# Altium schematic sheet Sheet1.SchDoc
size B; SheetNumber: 1; SheetTotal: 2
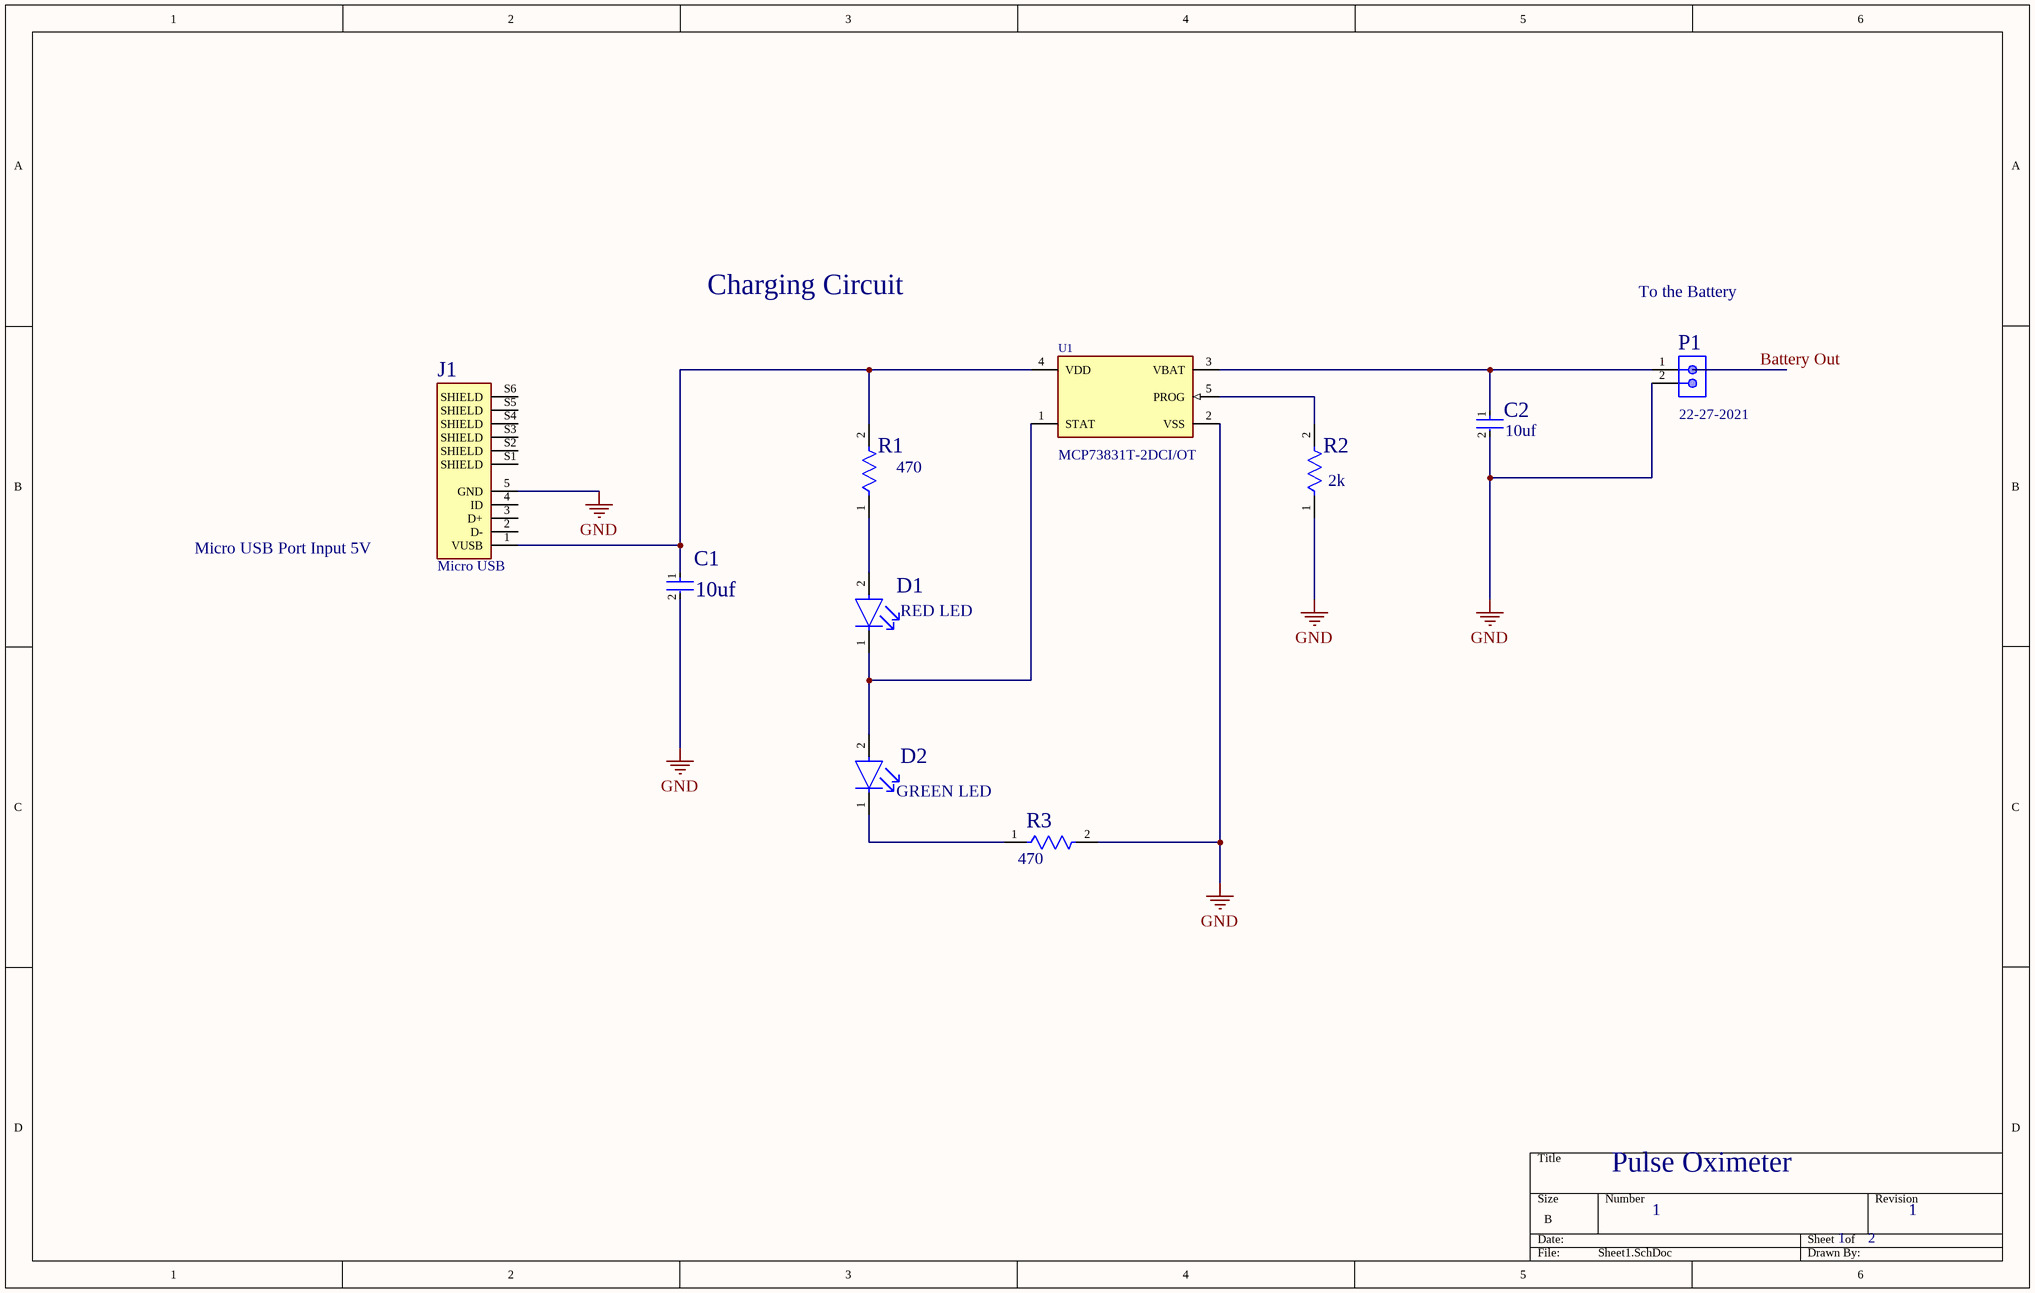
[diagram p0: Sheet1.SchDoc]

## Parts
C1  10uf  [FP-CL10-IPC_A]
C2  10uf  [FP-CL10-IPC_A]
D1  RED LED  [FP-HSMS-C150-MFG]
D2  GREEN LED  [FP-HSMG-C150-MFG]
J1  Micro USB  [AMPHENOL_10118193-0001LF]
P1  22-27-2021  [MOLX-22-27-2021_V]
R1  470  [FP-RC1608-MFG]
R2  2k  [FP-RC1608-MFG]
R3  470  [FP-RC1608-MFG]
U1  MCP73831T-2DCI/OT  [FP-C04-091-OT-IPC_B]

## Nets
GND: C1.2 C2.2 J1.5(GND) P1.2 R2.1 R3.2 U1.2(VSS)
NetC1_1: C1.1 J1.1(VUSB) R1.2 U1.4(VDD)
NetC2_1: C2.1 P1.1 U1.3(VBAT)
NetD1_1: D1.1(C) D2.2(A) U1.1(STAT)
NetD1_2: D1.2(A) R1.1
NetD2_1: D2.1(C) R3.1
NetR2_2: R2.2 U1.5(PROG)

Not connected (* = marked no-connect by the designer): J1 2(D-) 3(D+) 4(ID) S1(SHIELD) S2(SHIELD) S3(SHIELD) S4(SHIELD) S5(SHIELD) S6(SHIELD)

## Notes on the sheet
- Charging Circuit
- To the Battery
- Micro USB Port Input 5V
- Pulse Oximeter
- 1
- 2

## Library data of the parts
C1 C2 = CMP-13271-003121-1: Cap Ceramic 39pF 50V C0G ±2% Pad SMD 0603 +125°C T/R
D1 = CMP-21615-000001-1: LED RED DIFFUSED CHIP SMD; Luminous Intensity: 10mcd; Power Dissipation: 65mW; Viewing Angle: 170°; Number of Elements: 1; Forward Current: 20mA; Lens Color: White; Lens Style: Rectangular; Wavelength: 626nm; Forward Voltage: 2.1V; Reverse Voltage: 5V
D2 = CMP-2000-05061-2: LED GREEN DIFFUSED 1206 SMD; Manufacturer Part Number: HSMG-C150; Manufacturer: Broadcom; Led Orientation: Top View; Max Junction Temp: +95°C; Peak Emmision Wavelength: 570nm; Viewing Angle: 170°; Wavelength: 572nm; Reverse Voltage: 5V; Luminous Intensity: 15mcd; Description: Surface Mount Chip LEDs; Forward Voltage: 2.2V; Power Dissipation: 65mW; Forward Current: 20mA
J1 = 10118193-0001LF: Micro USB 2.0, Input Output Connectors, B TYPE RECEPTACLE; MF: Amphenol ICC
P1 = CMP-2000-05537-1: Male Header, Pitch 2.54 mm, 1 x 2 Position, Height 11.7 mm, Tail Length 3.56 mm, 0 to 75 degC, RoHS, Bulk; Manufacturer: Molex; PartNumber: 0022272021; Current rating: 4A; Package Version: Rev. BC, 02/2012; Voltage rating: 250V; No. of Positions: 2; Pitch: 2.54mm; No. of Rows: 1
R1-R3 = CMP-13261-003959-1: Res Thick Film 0603 270Ω 5% 0.1W ±100ppm/°C Molded SMD T/R; Resistance: 270R; Max Power Dissipation: 100mW; Voltage Rating (DC): 50V
U1 = CMP-0133-00146-2: IC CONTROLLR LI-ION 4.2V SOT23-5; Max Charge Current: 500mA; Min Output Voltage: 4.168V; Max Supply Voltage: 6V; Max Output Voltage: 4.232V; Number of Cells: 1; Operating Supply Current: 510uA; Min Supply Voltage: 3.75V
